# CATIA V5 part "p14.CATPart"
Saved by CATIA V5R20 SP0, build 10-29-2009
Part number: p14
Bounding box of the stored display mesh (mm): x -15 to -10, y -54.999 to -15.001, z 15.004 to 44.996
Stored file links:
  D:\Dropbox\IAO_2011\MMS_GR2\IAO_2011_1439_jlicbarski\p14.CATPart
  D:\Dropbox\IAO_2011\MMS_GR2\IAO_2011_1439_jlicbarski\train.CATProduct
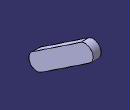
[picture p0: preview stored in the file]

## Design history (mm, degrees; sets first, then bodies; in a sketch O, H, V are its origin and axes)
AxisSystem1: origin (0, 0, 0), X (1, 0, 0), Y (0, 1, 0), Z (0, 0, 1)
Set1
  Plane1: linked copy from another document
  Line1: linked copy from another document
  Line2: linked copy from another document
Body1 (main body)
  Sketch1 on Plane1, origin (-10, 0, 0), H (0, 1, 0), V (0, 0, 1)
    arc A1 centre (-20, 40) radius 5 from (-17.2265, 35.8397) to (-22.7735, 44.1603) ccw
    arc A2 centre (-50, 20) radius 5 from (-52.7735, 24.1603) to (-47.2265, 15.8397) ccw
    point P3 (-52.7735, 24.1603)
    reference projected point E1 (-20, 40) from Line2
    reference projected point E2 (-50, 20) from Line1
    line L1 (-52.7735, 24.1603) -> (-22.7735, 44.1603)
    point P5 (-52.7735, 24.1603)
    line L2 (-47.2265, 15.8397) -> (-17.2265, 35.8397)
    radius A1 = 5
    distance A1 E1 = 5
    radius A2 = 5
    distance A2 E2 = 5
    coincidence: P3 P5
  Pad1: profile Sketch1, direction (-1, 0, 0), length 5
